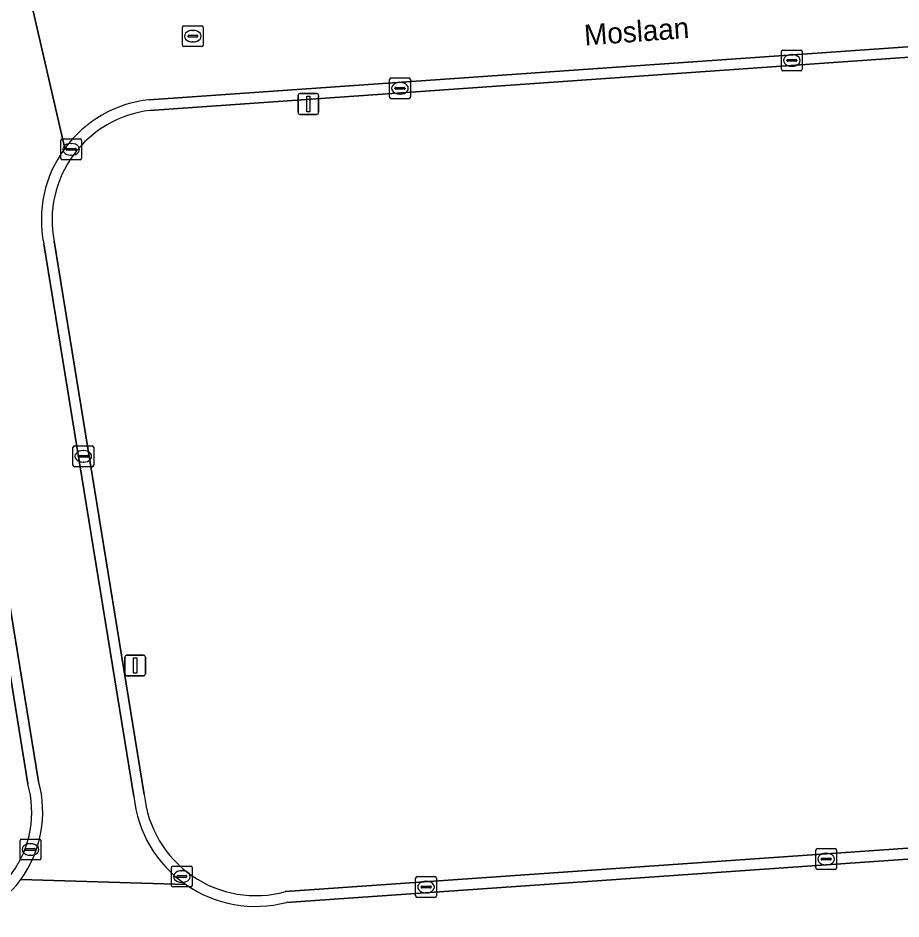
# Model space of a CAD drawing. Extents: x 162661 to 163484, y 380247 to 381230.
# Drawn here: x 163058.57 to 163101.01, y 380356.53 to 380399.85 of the extents above; entities that cross this region are included whole.
import ezdxf

# ---------------------------------------------------------------- set-up
doc = ezdxf.new("R2010")
doc.units = 0
for name, color, linetype in [('IMGEO_Groenvoorziening', 7, 'Continuous'), ('IMGEO_Kolk', 7, 'Continuous'), ('IMGEO_Lichtmast', 7, 'Continuous'), ('IMGEO_Openbare_ruimte_label', 7, 'Continuous'), ('IMGEO_Rijbaan_lokaal_gesloten', 7, 'Continuous'), ('IMGEO_Rijbaan_lokaal_open', 7, 'Continuous'), ('IMGEO_Rioolput', 7, 'Continuous')]:
    doc.layers.add(name, color=color, linetype=linetype)

msp = doc.modelspace()

# ---------------------------------------------------------------- linework, layer by layer
at = {"layer": 'IMGEO_Groenvoorziening'}
for points in [[(163071.431, 380357.843), (163126.19, 380361.661), (163126.78, 380397.532), (163126.755, 380399.742), (163064.909, 380395.406)], [(163060.304, 380389.124), (163064.64, 380362.514)], [(163059.044, 380363.035), (163057.264, 380373.948), (163007.348, 380365.222), (163008.76, 380353.55), (163054.471, 380356.654)]]:
    msp.add_lwpolyline(points, dxfattribs=at)
for centre, radius, start, end in [((163065.524, 380390.127), 5.315, 96.6403, 190.8733), ((163054.215, 380361.666), 5.019, 272.9186, 15.8262), ((163070.006, 380363.043), 5.392, 185.6352, 285.3227)]:
    msp.add_arc(centre, radius, start, end, dxfattribs=at)
at = {"layer": 'IMGEO_Kolk'}
for p, q in [((163095.267, 380397.387), (163095.267, 380398.239)), ((163095.342, 380398.313), (163096.194, 380398.313)), ((163096.268, 380398.239), (163096.268, 380397.387)), ((163095.526, 380397.807), (163095.526, 380397.819)), ((163095.964, 380397.77), (163095.566, 380397.77)), ((163095.569, 380397.856), (163095.967, 380397.856)), ((163095.755, 380398.093), (163095.78, 380398.093)), ((163096.01, 380397.819), (163096.01, 380397.807)), ((163096.194, 380397.313), (163095.342, 380397.313)), ((163095.778, 380397.533), (163095.753, 380397.533)), ((163076.431, 380396.047), (163076.431, 380396.899)), ((163076.506, 380396.973), (163077.358, 380396.973)), ((163077.432, 380396.899), (163077.432, 380396.047)), ((163076.69, 380396.467), (163076.69, 380396.479)), ((163077.128, 380396.43), (163076.73, 380396.43)), ((163076.733, 380396.516), (163077.131, 380396.516)), ((163076.919, 380396.753), (163076.944, 380396.753)), ((163077.174, 380396.479), (163077.174, 380396.467)), ((163076.942, 380396.193), (163076.917, 380396.193)), ((163077.358, 380395.973), (163076.506, 380395.973)), ((163060.626, 380393.112), (163060.626, 380393.964)), ((163060.701, 380394.038), (163061.553, 380394.038)), ((163061.627, 380393.964), (163061.627, 380393.112)), ((163060.885, 380393.532), (163060.885, 380393.544)), ((163061.323, 380393.495), (163060.925, 380393.495)), ((163060.928, 380393.581), (163061.326, 380393.581)), ((163061.114, 380393.818), (163061.139, 380393.818)), ((163061.369, 380393.544), (163061.369, 380393.532)), ((163061.553, 380393.038), (163060.701, 380393.038)), ((163061.137, 380393.258), (163061.112, 380393.258)), ((163061.211, 380378.352), (163061.211, 380379.204)), ((163061.286, 380379.278), (163062.138, 380379.278)), ((163062.212, 380379.204), (163062.212, 380378.352)), ((163061.47, 380378.772), (163061.47, 380378.784)), ((163061.908, 380378.735), (163061.51, 380378.735)), ((163061.513, 380378.821), (163061.911, 380378.821)), ((163061.699, 380379.058), (163061.724, 380379.058)), ((163061.954, 380378.784), (163061.954, 380378.772)), ((163062.138, 380378.278), (163061.286, 380378.278)), ((163061.722, 380378.498), (163061.697, 380378.498)), ((163058.669, 380359.445), (163058.669, 380360.297)), ((163058.744, 380360.371), (163059.596, 380360.371)), ((163059.157, 380360.151), (163059.182, 380360.151)), ((163059.67, 380360.297), (163059.67, 380359.445)), ((163058.928, 380359.865), (163058.928, 380359.877)), ((163059.366, 380359.828), (163058.968, 380359.828)), ((163058.971, 380359.914), (163059.369, 380359.914)), ((163059.412, 380359.877), (163059.412, 380359.865)), ((163096.919, 380358.986), (163096.919, 380359.838)), ((163096.994, 380359.912), (163097.846, 380359.912)), ((163097.407, 380359.692), (163097.432, 380359.692)), ((163097.92, 380359.838), (163097.92, 380358.986)), ((163059.596, 380359.371), (163058.744, 380359.371)), ((163059.18, 380359.591), (163059.155, 380359.591)), ((163097.178, 380359.406), (163097.178, 380359.418)), ((163097.616, 380359.369), (163097.218, 380359.369)), ((163097.221, 380359.455), (163097.619, 380359.455)), ((163097.662, 380359.418), (163097.662, 380359.406)), ((163065.95, 380358.145), (163065.95, 380358.997)), ((163066.025, 380359.071), (163066.877, 380359.071)), ((163066.438, 380358.851), (163066.463, 380358.851)), ((163066.951, 380358.997), (163066.951, 380358.145)), ((163097.846, 380358.912), (163096.994, 380358.912)), ((163097.43, 380359.132), (163097.405, 380359.132)), ((163066.209, 380358.565), (163066.209, 380358.577)), ((163066.647, 380358.528), (163066.249, 380358.528)), ((163066.252, 380358.614), (163066.65, 380358.614)), ((163066.693, 380358.577), (163066.693, 380358.565)), ((163077.685, 380357.639), (163077.685, 380358.491)), ((163077.76, 380358.565), (163078.612, 380358.565)), ((163078.173, 380358.345), (163078.198, 380358.345)), ((163078.686, 380358.491), (163078.686, 380357.639)), ((163066.877, 380358.071), (163066.025, 380358.071)), ((163066.461, 380358.291), (163066.436, 380358.291)), ((163077.944, 380358.059), (163077.944, 380358.071)), ((163078.382, 380358.022), (163077.984, 380358.022)), ((163077.987, 380358.108), (163078.385, 380358.108)), ((163078.428, 380358.071), (163078.428, 380358.059)), ((163078.612, 380357.565), (163077.76, 380357.565)), ((163078.196, 380357.785), (163078.171, 380357.785))]:
    msp.add_line(p, q, dxfattribs=at)
for points in [[(163095.267, 380397.387), (163095.267, 380398.239)], [(163095.342, 380398.313), (163096.194, 380398.313)], [(163096.268, 380398.239), (163096.268, 380397.387)], [(163096.194, 380397.313), (163095.342, 380397.313)], [(163076.431, 380396.047), (163076.431, 380396.899)], [(163076.506, 380396.973), (163077.358, 380396.973)], [(163077.432, 380396.899), (163077.432, 380396.047)], [(163077.358, 380395.973), (163076.506, 380395.973)], [(163060.626, 380393.112), (163060.626, 380393.964)], [(163060.701, 380394.038), (163061.553, 380394.038)], [(163061.627, 380393.964), (163061.627, 380393.112)], [(163061.553, 380393.038), (163060.701, 380393.038)], [(163061.211, 380378.352), (163061.211, 380379.204)], [(163061.286, 380379.278), (163062.138, 380379.278)], [(163062.212, 380379.204), (163062.212, 380378.352)], [(163062.138, 380378.278), (163061.286, 380378.278)], [(163058.669, 380359.445), (163058.669, 380360.297)], [(163058.744, 380360.371), (163059.596, 380360.371)], [(163059.67, 380360.297), (163059.67, 380359.445)], [(163096.919, 380358.986), (163096.919, 380359.838)], [(163096.994, 380359.912), (163097.846, 380359.912)], [(163097.92, 380359.838), (163097.92, 380358.986)], [(163059.596, 380359.371), (163058.744, 380359.371)], [(163065.95, 380358.145), (163065.95, 380358.997)], [(163066.025, 380359.071), (163066.877, 380359.071)], [(163066.951, 380358.997), (163066.951, 380358.145)], [(163097.846, 380358.912), (163096.994, 380358.912)], [(163077.685, 380357.639), (163077.685, 380358.491)], [(163077.76, 380358.565), (163078.612, 380358.565)], [(163078.686, 380358.491), (163078.686, 380357.639)], [(163066.877, 380358.071), (163066.025, 380358.071)], [(163078.612, 380357.565), (163077.76, 380357.565)]]:
    msp.add_lwpolyline(points, dxfattribs=at)
for centre, radius, start, end in [((163095.344, 380398.237), 0.0765, 91.552, 178.448), ((163095.344, 380398.237), 0.0765, 91.552, 178.448), ((163096.192, 380398.237), 0.0765, 1.552, 88.448), ((163096.192, 380398.237), 0.0765, 1.552, 88.448), ((163095.566, 380397.816), 0.0403, 85.8775, 175.7526), ((163095.563, 380397.806), 0.0366, 178.938, 274.7102), ((163095.967, 380397.813), 0.043, 264.8664, 352.4533), ((163095.971, 380397.818), 0.0386, 1.7309, 96.639), ((163095.344, 380397.389), 0.0765, 181.552, 268.448), ((163095.344, 380397.389), 0.0765, 181.552, 268.448), ((163096.192, 380397.389), 0.0765, 271.552, 358.448), ((163096.192, 380397.389), 0.0765, 271.552, 358.448), ((163076.508, 380396.897), 0.0765, 91.552, 178.448), ((163076.508, 380396.897), 0.0765, 91.552, 178.448), ((163077.356, 380396.897), 0.0765, 1.552, 88.448), ((163077.356, 380396.897), 0.0765, 1.552, 88.448), ((163076.73, 380396.476), 0.0403, 85.8775, 175.7526), ((163076.727, 380396.466), 0.0366, 178.938, 274.7102), ((163077.131, 380396.473), 0.043, 264.8664, 352.4533), ((163077.135, 380396.478), 0.0386, 1.7309, 96.639), ((163076.508, 380396.049), 0.0765, 181.552, 268.448), ((163076.508, 380396.049), 0.0765, 181.552, 268.448), ((163077.356, 380396.049), 0.0765, 271.552, 358.448), ((163077.356, 380396.049), 0.0765, 271.552, 358.448), ((163060.703, 380393.962), 0.0765, 91.552, 178.448), ((163060.703, 380393.962), 0.0765, 91.552, 178.448), ((163061.551, 380393.962), 0.0765, 1.552, 88.448), ((163061.551, 380393.962), 0.0765, 1.552, 88.448), ((163060.925, 380393.541), 0.0403, 85.8775, 175.7526), ((163060.922, 380393.531), 0.0366, 178.938, 274.7102), ((163061.326, 380393.538), 0.043, 264.8664, 352.4533), ((163061.33, 380393.543), 0.0386, 1.7309, 96.639), ((163060.703, 380393.114), 0.0765, 181.552, 268.448), ((163060.703, 380393.114), 0.0765, 181.552, 268.448), ((163061.551, 380393.114), 0.0765, 271.552, 358.448), ((163061.551, 380393.114), 0.0765, 271.552, 358.448), ((163061.288, 380379.202), 0.0765, 91.552, 178.448), ((163061.288, 380379.202), 0.0765, 91.552, 178.448), ((163062.136, 380379.202), 0.0765, 1.552, 88.448), ((163062.136, 380379.202), 0.0765, 1.552, 88.448), ((163061.51, 380378.781), 0.0403, 85.8775, 175.7526), ((163061.507, 380378.771), 0.0366, 178.938, 274.7102), ((163061.911, 380378.778), 0.043, 264.8664, 352.4533), ((163061.915, 380378.783), 0.0386, 1.7309, 96.639), ((163061.288, 380378.354), 0.0765, 181.552, 268.448), ((163061.288, 380378.354), 0.0765, 181.552, 268.448), ((163062.136, 380378.354), 0.0765, 271.552, 358.448), ((163062.136, 380378.354), 0.0765, 271.552, 358.448), ((163058.746, 380360.295), 0.0765, 91.552, 178.448), ((163058.746, 380360.295), 0.0765, 91.552, 178.448), ((163059.594, 380360.295), 0.0765, 1.552, 88.448), ((163059.594, 380360.295), 0.0765, 1.552, 88.448), ((163058.968, 380359.874), 0.0403, 85.8775, 175.7526), ((163058.965, 380359.864), 0.0366, 178.938, 274.7102), ((163059.369, 380359.871), 0.043, 264.8664, 352.4533), ((163059.373, 380359.876), 0.0386, 1.7309, 96.639), ((163096.996, 380359.836), 0.0765, 91.552, 178.448), ((163096.996, 380359.836), 0.0765, 91.552, 178.448), ((163097.844, 380359.836), 0.0765, 1.552, 88.448), ((163097.844, 380359.836), 0.0765, 1.552, 88.448), ((163058.746, 380359.447), 0.0765, 181.552, 268.448), ((163058.746, 380359.447), 0.0765, 181.552, 268.448), ((163059.594, 380359.447), 0.0765, 271.552, 358.448), ((163059.594, 380359.447), 0.0765, 271.552, 358.448), ((163097.218, 380359.415), 0.0403, 85.8775, 175.7526), ((163097.215, 380359.405), 0.0366, 178.938, 274.7102), ((163097.619, 380359.412), 0.043, 264.8664, 352.4533), ((163097.623, 380359.417), 0.0386, 1.7309, 96.639), ((163066.027, 380358.995), 0.0765, 91.552, 178.448), ((163066.027, 380358.995), 0.0765, 91.552, 178.448), ((163066.875, 380358.995), 0.0765, 1.552, 88.448), ((163066.875, 380358.995), 0.0765, 1.552, 88.448), ((163096.996, 380358.988), 0.0765, 181.552, 268.448), ((163096.996, 380358.988), 0.0765, 181.552, 268.448), ((163097.844, 380358.988), 0.0765, 271.552, 358.448), ((163097.844, 380358.988), 0.0765, 271.552, 358.448), ((163066.249, 380358.574), 0.0403, 85.8775, 175.7526), ((163066.246, 380358.564), 0.0366, 178.938, 274.7102), ((163066.65, 380358.571), 0.043, 264.8664, 352.4533), ((163066.654, 380358.576), 0.0386, 1.7309, 96.639), ((163077.762, 380358.489), 0.0765, 91.552, 178.448), ((163077.762, 380358.489), 0.0765, 91.552, 178.448), ((163078.61, 380358.489), 0.0765, 1.552, 88.448), ((163078.61, 380358.489), 0.0765, 1.552, 88.448), ((163066.027, 380358.147), 0.0765, 181.552, 268.448), ((163066.027, 380358.147), 0.0765, 181.552, 268.448), ((163066.875, 380358.147), 0.0765, 271.552, 358.448), ((163066.875, 380358.147), 0.0765, 271.552, 358.448), ((163077.984, 380358.068), 0.0403, 85.8775, 175.7526), ((163077.981, 380358.058), 0.0366, 178.938, 274.7102), ((163078.385, 380358.065), 0.043, 264.8664, 352.4533), ((163078.389, 380358.07), 0.0386, 1.7309, 96.639), ((163077.762, 380357.641), 0.0765, 181.552, 268.448), ((163077.762, 380357.641), 0.0765, 181.552, 268.448), ((163078.61, 380357.641), 0.0765, 271.552, 358.448), ((163078.61, 380357.641), 0.0765, 271.552, 358.448)]:
    msp.add_arc(centre, radius, start, end, dxfattribs=at)
for centre, major_axis, ratio, start_param, end_param in [((163095.754, 380397.813), (-0.387, 0.002), 0.722429, 4.712389, 7.853982), ((163095.779, 380397.813), (-0.39, 0.002), 0.717154, 1.570796, 4.712389), ((163076.918, 380396.473), (-0.387, 0.002), 0.722429, 4.712389, 7.853982), ((163076.943, 380396.473), (-0.39, 0.002), 0.717154, 1.570796, 4.712389), ((163061.113, 380393.538), (-0.387, 0.002), 0.722429, 4.712389, 7.853982), ((163061.138, 380393.538), (-0.39, 0.002), 0.717154, 1.570796, 4.712389), ((163061.698, 380378.778), (-0.387, 0.002), 0.722429, 4.712389, 7.853982), ((163061.723, 380378.778), (-0.39, 0.002), 0.717154, 1.570796, 4.712389), ((163059.156, 380359.871), (-0.387, 0.002), 0.722429, 4.712389, 7.853982), ((163059.181, 380359.871), (-0.39, 0.002), 0.717154, 1.570796, 4.712389), ((163097.406, 380359.412), (-0.387, 0.002), 0.722429, 4.712389, 7.853982), ((163097.431, 380359.412), (-0.39, 0.002), 0.717154, 1.570796, 4.712389), ((163066.437, 380358.571), (-0.387, 0.002), 0.722429, 4.712389, 7.853982), ((163066.462, 380358.571), (-0.39, 0.002), 0.717154, 1.570796, 4.712389), ((163078.172, 380358.065), (-0.387, 0.002), 0.722429, 4.712389, 7.853982), ((163078.197, 380358.065), (-0.39, 0.002), 0.717154, 1.570796, 4.712389)]:
    msp.add_ellipse(centre, major_axis=major_axis, ratio=ratio, start_param=start_param, end_param=end_param, dxfattribs=at)
at = {"layer": 'IMGEO_Lichtmast'}
for p, q in [((163072.032, 380395.32), (163072.032, 380396.12)), ((163072.032, 380396.12), (163072.032, 380395.32)), ((163072.132, 380396.22), (163072.922, 380396.22)), ((163072.922, 380396.22), (163072.132, 380396.22)), ((163073.022, 380396.12), (163073.022, 380395.32)), ((163073.022, 380395.32), (163073.022, 380396.12)), ((163072.922, 380395.22), (163072.132, 380395.22)), ((163072.132, 380395.22), (163072.922, 380395.22)), ((163063.81, 380369.218), (163064.6, 380369.218)), ((163064.6, 380369.218), (163063.81, 380369.218)), ((163063.71, 380368.318), (163063.71, 380369.118)), ((163063.71, 380369.118), (163063.71, 380368.318)), ((163064.7, 380369.118), (163064.7, 380368.318)), ((163064.7, 380368.318), (163064.7, 380369.118)), ((163064.6, 380368.218), (163063.81, 380368.218)), ((163063.81, 380368.218), (163064.6, 380368.218))]:
    msp.add_line(p, q, dxfattribs=at)
for points in [[(163072.452, 380396.095), (163072.602, 380396.095), (163072.602, 380395.345), (163072.452, 380395.345), (163072.452, 380396.095)], [(163064.13, 380369.093), (163064.28, 380369.093), (163064.28, 380368.343), (163064.13, 380368.343), (163064.13, 380369.093)]]:
    msp.add_lwpolyline(points, dxfattribs=at)
for centre, start, end in [((163072.132, 380396.12), 90, 180), ((163072.132, 380396.12), 90, 180), ((163072.922, 380396.12), 0, 90), ((163072.922, 380396.12), 360, 90), ((163072.132, 380395.32), 180, 270), ((163072.132, 380395.32), 180, 270), ((163072.922, 380395.32), 270, 0), ((163072.922, 380395.32), 270, 0), ((163063.81, 380369.118), 90, 180), ((163063.81, 380369.118), 90, 180), ((163064.6, 380369.118), 0, 90), ((163064.6, 380369.118), 360, 90), ((163063.81, 380368.318), 180, 270), ((163063.81, 380368.318), 180, 270), ((163064.6, 380368.318), 270, 0), ((163064.6, 380368.318), 270, 0)]:
    msp.add_arc(centre, 0.1, start, end, dxfattribs=at)
at = {"layer": 'IMGEO_Rijbaan_lokaal_gesloten'}
for points in [[(163057.38, 380403.975), (163052.079, 380436.342), (163048.058, 380433.778), (163059.565, 380363.138)], [(163064.883, 380395.926), (163126.779, 380400.24), (163126.503, 380404.662)], [(163059.103, 380401.035), (163060.816, 380393.582)], [(163060.816, 380393.582), (163059.103, 380401.035)], [(163064.142, 380362.419), (163059.809, 380388.997)], [(163129.13, 380361.35), (163071.476, 380357.328)], [(163066.635, 380358.182), (163058.705, 380358.425)], [(163058.705, 380358.425), (163066.635, 380358.182)]]:
    msp.add_lwpolyline(points, dxfattribs=at)
for centre, radius, start, end in [((163065.503, 380390.15), 5.809, 96.1255, 143.7882), ((163065.505, 380390.149), 5.811, 143.7909, 191.4348), ((163054.212, 380361.68), 5.548, 324.0775, 15.24), ((163069.978, 380363.001), 5.865, 185.6955, 235.2486), ((163054.212, 380361.684), 5.55, 272.898, 324.0405), ((163069.982, 380363.007), 5.872, 235.2501, 284.7407)]:
    msp.add_arc(centre, radius, start, end, dxfattribs=at)
at = {"layer": 'IMGEO_Rijbaan_lokaal_open'}
for points in [[(163059.565, 380363.138), (163048.058, 380433.778), (163047.522, 380433.648), (163047.603, 380433.152), (163056.95, 380375.873), (163057.264, 380373.948), (163059.044, 380363.035)], [(163126.779, 380400.24), (163064.883, 380395.926)], [(163064.909, 380395.406), (163126.755, 380399.742)], [(163064.64, 380362.514), (163060.304, 380389.124)], [(163059.809, 380388.997), (163064.142, 380362.419)], [(163129.108, 380361.865), (163128.149, 380361.798), (163126.19, 380361.661), (163071.431, 380357.843)], [(163071.476, 380357.328), (163129.13, 380361.35)]]:
    msp.add_lwpolyline(points, dxfattribs=at)
for centre, radius, start, end in [((163065.503, 380390.15), 5.809, 96.1255, 143.7882), ((163065.524, 380390.127), 5.315, 96.6403, 190.8733), ((163065.505, 380390.149), 5.811, 143.7909, 191.4348), ((163054.212, 380361.68), 5.548, 324.0775, 15.24), ((163054.215, 380361.666), 5.019, 272.9186, 15.8262), ((163069.978, 380363.001), 5.865, 185.6955, 235.2486), ((163070.006, 380363.043), 5.392, 185.6352, 285.3227), ((163054.212, 380361.684), 5.55, 272.898, 324.0405), ((163069.982, 380363.007), 5.872, 235.2501, 284.7407)]:
    msp.add_arc(centre, radius, start, end, dxfattribs=at)
at = {"layer": 'IMGEO_Rioolput'}
for p, q in [((163066.551, 380399.48), (163067.403, 380399.48)), ((163066.476, 380398.554), (163066.476, 380399.406)), ((163066.964, 380399.26), (163066.989, 380399.26)), ((163067.477, 380399.406), (163067.477, 380398.554)), ((163066.735, 380398.974), (163066.735, 380398.986)), ((163067.173, 380398.937), (163066.775, 380398.937)), ((163066.778, 380399.023), (163067.176, 380399.023)), ((163066.987, 380398.7), (163066.962, 380398.7)), ((163067.219, 380398.986), (163067.219, 380398.974)), ((163067.403, 380398.48), (163066.551, 380398.48))]:
    msp.add_line(p, q, dxfattribs=at)
for points in [[(163066.551, 380399.48), (163067.403, 380399.48)], [(163066.476, 380398.554), (163066.476, 380399.406)], [(163067.477, 380399.406), (163067.477, 380398.554)], [(163067.403, 380398.48), (163066.551, 380398.48)]]:
    msp.add_lwpolyline(points, dxfattribs=at)
for centre, radius, start, end in [((163066.553, 380399.404), 0.0765, 91.552, 178.448), ((163066.553, 380399.404), 0.0765, 91.552, 178.448), ((163067.401, 380399.404), 0.0765, 1.552, 88.448), ((163067.401, 380399.404), 0.0765, 1.552, 88.448), ((163066.775, 380398.983), 0.0403, 85.8775, 175.7526), ((163066.772, 380398.973), 0.0366, 178.938, 274.7102), ((163067.176, 380398.98), 0.043, 264.8664, 352.4533), ((163067.18, 380398.985), 0.0386, 1.7309, 96.639), ((163066.553, 380398.556), 0.0765, 181.552, 268.448), ((163066.553, 380398.556), 0.0765, 181.552, 268.448), ((163067.401, 380398.556), 0.0765, 271.552, 358.448), ((163067.401, 380398.556), 0.0765, 271.552, 358.448)]:
    msp.add_arc(centre, radius, start, end, dxfattribs=at)
for centre, major_axis, ratio, start_param, end_param in [((163066.963, 380398.98), (-0.387, 0.002), 0.722429, 4.712389, 7.853982), ((163066.988, 380398.98), (-0.39, 0.002), 0.717154, 1.570796, 4.712389)]:
    msp.add_ellipse(centre, major_axis=major_axis, ratio=ratio, start_param=start_param, end_param=end_param, dxfattribs=at)

# ---------------------------------------------------------------- texts
at = {"layer": 'IMGEO_Openbare_ruimte_label'}
msp.add_text('Moslaan', height=1, rotation=4.1877, dxfattribs=at).set_placement((163085.82, 380398.527))

doc.saveas('drawing.dxf')
